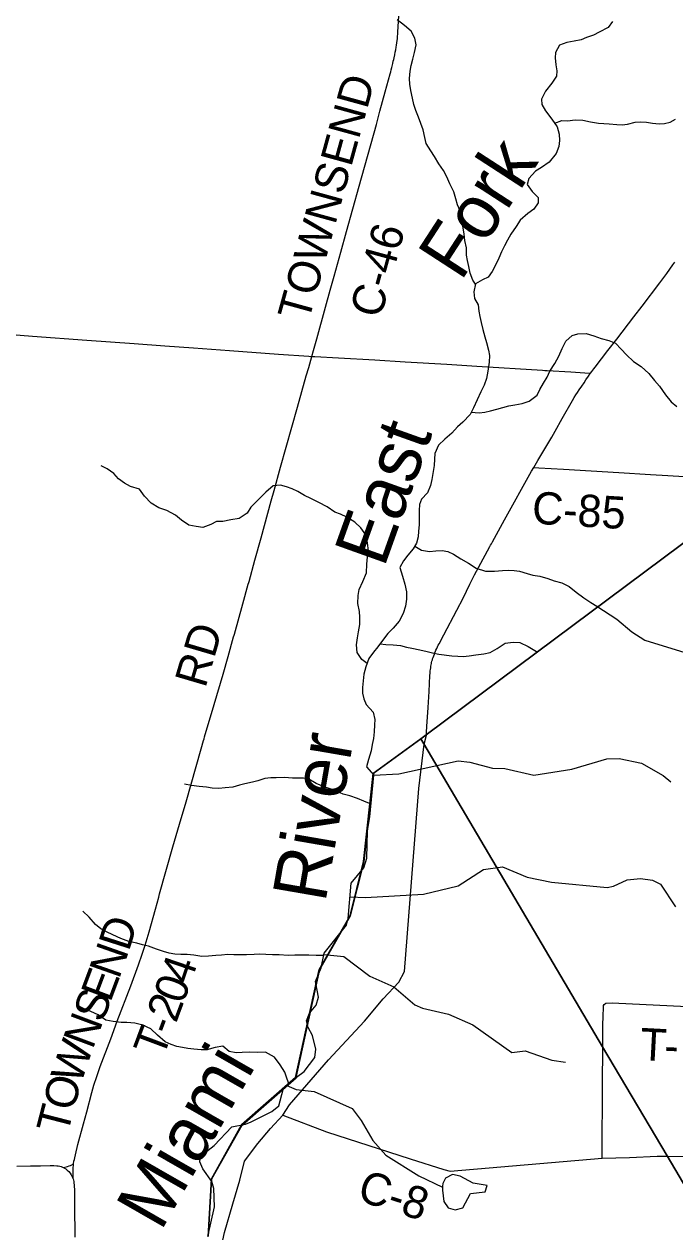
# Model space of a CAD drawing. Extents: x 0 to 1052, y -194 to 246.
# Drawn here: x 2.989 to 4.134, y 15.72 to 17.846 of the extents above; entities that cross this region are included whole.
import ezdxf

# ---------------------------------------------------------------- set-up
doc = ezdxf.new("R2010")
doc.units = 0
for name, color, linetype in [('GM_X_Corporation', 7, 'Continuous'), ('GM_X_County_Road', 7, 'Continuous'), ('GM_X_County_Road_Text', 7, 'Continuous'), ('GM_X_Major_River', 7, 'Continuous'), ('GM_X_Major_River_Text', 7, 'Continuous'), ('GM_X_Minor_Lake', 7, 'Continuous'), ('GM_X_Minor_River', 7, 'Continuous'), ('GM_X_State_Route', 7, 'Continuous'), ('GM_X_Township_Road', 7, 'Continuous'), ('GM_X_Township_Road_Text', 7, 'Continuous')]:
    doc.layers.add(name, color=color, linetype=linetype)

msp = doc.modelspace()

# ---------------------------------------------------------------- linework, layer by layer
at = {"layer": 'GM_X_Corporation'}
for points in [[(5.491, 17.9457), (5.1788, 17.6981), (4.2749, 17.0262), (3.6964, 16.595), (3.6869, 16.5875), (3.6921, 16.5787), (4.0068, 16.0455), (4.1203, 15.8533), (4.4065, 15.3682), (5.0927, 14.2055), (8.7822, 14.2055), (8.7822, 19.8853)], [(4.2749, 17.0262), (3.6964, 16.595), (3.6869, 16.5875), (3.603, 16.5265), (3.586, 16.3718), (3.5622, 16.2766), (3.508, 16.1818), (3.4664, 15.9915), (3.3714, 15.908), (3.3184, 15.8132), (3.3123, 15.7116)], [(3.3123, 15.7116), (3.3184, 15.8132), (3.3714, 15.908), (3.4664, 15.9915), (3.508, 16.1818), (3.5622, 16.2766), (3.586, 16.3718), (3.603, 16.5265), (3.6869, 16.5875), (3.6964, 16.595), (4.2749, 17.0262)], [(3.3123, 15.7116), (3.3184, 15.8132), (3.3714, 15.908), (3.4664, 15.9915), (3.508, 16.1818), (3.5622, 16.2766), (3.586, 16.3718), (3.603, 16.5265), (3.6869, 16.5875), (3.6964, 16.595), (4.2749, 17.0262)], [(4.4065, 15.3682), (4.1203, 15.8533), (4.0068, 16.0455), (3.6921, 16.5787), (3.6869, 16.5875), (3.603, 16.5265), (3.586, 16.3718), (3.5622, 16.2766), (3.508, 16.1818), (3.4664, 15.9915), (3.3714, 15.908), (3.3184, 15.8132), (3.3123, 15.7116)]]:
    msp.add_lwpolyline(points, dxfattribs=at)
at = {"layer": 'GM_X_County_Road'}
for points in [[(3.4947, 17.261), (3.4976, 17.2712), (3.5035, 17.2921), (3.5189, 17.3478), (3.5274, 17.3777), (3.534, 17.4023), (3.5459, 17.4448), (3.5558, 17.4807), (3.5783, 17.5609), (3.6085, 17.6692), (3.6147, 17.6926), (3.6241, 17.7267), (3.6327, 17.7585), (3.6337, 17.7621), (3.6346, 17.7659), (3.6355, 17.7695), (3.6373, 17.7768), (3.6383, 17.7808), (3.639, 17.784), (3.6396, 17.787), (3.6408, 17.7923), (3.6417, 17.7966), (3.6426, 17.8011), (3.6434, 17.8054), (3.644, 17.8089), (3.6446, 17.8131), (3.6451, 17.8171), (3.6455, 17.82), (3.6459, 17.8246), (3.6463, 17.8286), (3.6466, 17.8318), (3.6482, 17.8609)], [(2.9236, 17.303), (3.0035, 17.2967), (3.099, 17.2899), (3.182, 17.2838), (3.2365, 17.2798), (3.2867, 17.2762), (3.3499, 17.2714), (3.4361, 17.2652), (3.4894, 17.2613), (3.4947, 17.261)], [(3.4947, 17.261), (3.5005, 17.2607), (3.5421, 17.2585), (3.606, 17.2549), (3.6593, 17.2516), (3.7325, 17.2473), (3.7852, 17.2438), (3.9011, 17.2367), (3.9049, 17.2365), (3.9092, 17.2363), (3.9508, 17.2339), (3.9756, 17.2322), (3.9855, 17.2313)], [(3.8855, 17.0657), (3.8945, 17.0651), (3.9379, 17.0625), (4.0353, 17.0565), (4.0912, 17.053), (4.1216, 17.0513), (4.2171, 17.0454), (4.245, 17.0437), (4.2555, 17.0431), (4.2636, 17.0425), (4.2655, 17.0423), (4.2672, 17.0418), (4.2696, 17.0409), (4.2711, 17.04), (4.2725, 17.0387), (4.2735, 17.0372), (4.274, 17.0361), (4.2745, 17.0349), (4.2748, 17.0338), (4.2751, 17.0325), (4.2753, 17.0297), (4.2751, 17.0257)], [(3.4438, 15.9251), (3.5208, 15.8958), (3.6683, 15.8481), (3.7274, 15.8293), (3.7384, 15.8266), (4.0062, 15.8493), (4.054, 15.8506), (4.1026, 15.853), (4.1205, 15.8527), (4.2609, 15.8504)], [(2.9759, 15.8354), (2.9995, 15.8359), (3.0175, 15.8362), (3.0343, 15.8365), (3.0411, 15.8364), (3.046, 15.8362), (3.0484, 15.8358), (3.0514, 15.8353), (3.0537, 15.8346), (3.056, 15.8338), (3.0579, 15.8328)], [(3.0579, 15.8328), (3.0587, 15.8324), (3.0617, 15.8306), (3.0646, 15.8283), (3.0672, 15.8258), (3.0695, 15.823), (3.0715, 15.82), (3.0731, 15.8167), (3.0746, 15.8129)], [(3.0746, 15.8129), (3.0758, 15.8081), (3.0762, 15.8057), (3.0766, 15.8026), (3.0769, 15.7989), (3.0771, 15.7946), (3.0774, 15.7661), (3.0779, 15.7101)]]:
    msp.add_lwpolyline(points, dxfattribs=at)
at = {"layer": 'GM_X_Major_River'}
for points in [[(4.0241, 17.8505), (4.0167, 17.8404), (4.0009, 17.832), (3.9906, 17.8265), (3.9783, 17.8226), (3.9688, 17.8186), (3.9569, 17.8158), (3.944, 17.8138), (3.931, 17.8091), (3.9239, 17.7964), (3.9233, 17.7865), (3.9242, 17.7744), (3.9259, 17.7637), (3.9253, 17.7542), (3.9174, 17.7422), (3.9061, 17.728), (3.899, 17.7141), (3.8999, 17.7046), (3.9065, 17.6935), (3.9176, 17.6789), (3.9268, 17.6654), (3.93, 17.6524), (3.9308, 17.641), (3.9299, 17.6308), (3.9247, 17.6184), (3.9126, 17.6031), (3.8991, 17.5938), (3.8887, 17.5872), (3.8771, 17.5742), (3.8738, 17.564), (3.8826, 17.5513), (3.8931, 17.5408), (3.8932, 17.5313), (3.8858, 17.5205), (3.8754, 17.5124), (3.8618, 17.5009), (3.8544, 17.4896), (3.8454, 17.4765), (3.8395, 17.4656), (3.8343, 17.4559), (3.8288, 17.4454), (3.824, 17.4341), (3.8192, 17.4239)], [(3.8192, 17.4239), (3.8125, 17.4104), (3.8051, 17.4007), (3.7951, 17.396), (3.7832, 17.3886), (3.7802, 17.375), (3.7811, 17.3628), (3.7877, 17.3517), (3.789, 17.341), (3.7907, 17.3315), (3.7928, 17.3209), (3.7959, 17.3083), (3.7994, 17.2957), (3.8023, 17.2858), (3.8061, 17.272), (3.8075, 17.2625), (3.8068, 17.2507), (3.805, 17.2352), (3.8024, 17.2224), (3.798, 17.2103), (3.7924, 17.1987), (3.7857, 17.1848), (3.7797, 17.1708), (3.7734, 17.1588), (3.761, 17.1454), (3.7513, 17.1369), (3.7416, 17.1261), (3.7288, 17.1153), (3.7176, 17.1049), (3.7112, 17.0899), (3.711, 17.0804), (3.71, 17.069), (3.7078, 17.0547), (3.7061, 17.0444), (3.7036, 17.0335), (3.6987, 17.0207), (3.6879, 17.0099), (3.6842, 17.0001), (3.6836, 16.9895), (3.6838, 16.9766), (3.6839, 16.9644), (3.6829, 16.9535), (3.6819, 16.9436), (3.6794, 16.9323), (3.6735, 16.9225), (3.6638, 16.9113), (3.656, 16.9012), (3.65, 16.8892), (3.6543, 16.8743), (3.6585, 16.8598), (3.6616, 16.8465), (3.6617, 16.8336), (3.6596, 16.8215), (3.6555, 16.8083), (3.6484, 16.7948), (3.6379, 16.7828), (3.629, 16.7731), (3.6212, 16.7631), (3.611, 16.75), (3.6036, 16.7403), (3.5954, 16.729), (3.5902, 16.7147), (3.5865, 16.7019), (3.5855, 16.6898), (3.5841, 16.678), (3.5839, 16.6682), (3.5863, 16.6579), (3.5903, 16.6483), (3.6029, 16.6348), (3.6056, 16.6218), (3.6054, 16.6123), (3.6048, 16.5998), (3.6034, 16.5881), (3.6013, 16.5775), (3.5992, 16.5669), (3.5947, 16.5514), (3.5914, 16.5382), (3.604, 16.5237)], [(3.3118, 15.7115), (3.3234, 15.7637), (3.3227, 15.796), (3.3187, 15.8086), (3.303, 15.8308), (3.2979, 15.843), (3.2991, 15.8532), (3.3233, 15.8719), (3.3544, 15.9049), (3.378, 15.9095), (3.3883, 15.9132), (3.4246, 15.9317), (3.4368, 15.9415), (3.4444, 15.9706), (3.4567, 15.9837), (3.4812, 16.002), (3.5001, 16.0268), (3.5022, 16.0416), (3.4961, 16.0652), (3.4883, 16.0793), (3.4858, 16.0915), (3.4909, 16.1047), (3.5028, 16.1186), (3.5068, 16.133), (3.5015, 16.1607), (3.5116, 16.1845), (3.5165, 16.2106), (3.5558, 16.2595), (3.5586, 16.2716), (3.564, 16.3334), (3.5867, 16.3608), (3.5919, 16.3774), (3.5932, 16.4256), (3.597, 16.4502), (3.604, 16.5237)], [(3.3131, 15.7113), (3.3192, 15.8129), (3.3722, 15.9077), (3.4672, 15.9911), (3.5089, 16.1815), (3.563, 16.2763), (3.5868, 16.3714), (3.6039, 16.5262)]]:
    msp.add_lwpolyline(points, dxfattribs=at)
at = {"layer": 'GM_X_Minor_Lake'}
for points in [[(3.7248, 15.7934), (3.7272, 15.7729), (3.735, 15.7622), (3.7475, 15.7586), (3.7608, 15.7622), (3.7744, 15.7875), (3.8003, 15.7902), (3.8038, 15.8016), (3.7788, 15.8057), (3.7562, 15.8177), (3.7426, 15.8205), (3.73, 15.8142)], [(3.73, 15.8142), (3.7257, 15.8048), (3.7251, 15.8003), (3.7248, 15.7934)]]:
    msp.add_lwpolyline(points, dxfattribs=at)
at = {"layer": 'GM_X_Minor_River'}
for points in [[(3.7831, 17.3883), (3.7783, 17.3952), (3.7735, 17.4078), (3.7714, 17.4192), (3.7692, 17.4299), (3.7671, 17.4394), (3.7669, 17.4523), (3.7644, 17.4649), (3.763, 17.4763), (3.7613, 17.4873), (3.7591, 17.498), (3.7578, 17.5082), (3.7556, 17.5185), (3.7512, 17.5281), (3.7483, 17.5384), (3.7447, 17.5509), (3.738, 17.5651), (3.7325, 17.5773), (3.7266, 17.5884), (3.7187, 17.5999), (3.7106, 17.6133), (3.7046, 17.6232), (3.6961, 17.6362), (3.6939, 17.6465), (3.6911, 17.6598), (3.687, 17.6709), (3.6826, 17.6823), (3.6782, 17.6942), (3.6746, 17.7048), (3.6721, 17.7155), (3.6692, 17.7292), (3.6674, 17.7402), (3.6668, 17.7505), (3.6678, 17.763), (3.6698, 17.7732), (3.6726, 17.7846), (3.6758, 17.7959), (3.6783, 17.8099), (3.6765, 17.8214), (3.6698, 17.8336), (3.6578, 17.8436), (3.6454, 17.8536)], [(3.9224, 17.6718), (3.9351, 17.6764), (3.945, 17.6759), (3.9587, 17.6776), (3.972, 17.6771), (3.9856, 17.6738), (3.9993, 17.6718), (4.0087, 17.6709), (4.0182, 17.6704), (4.0315, 17.6691), (4.041, 17.669), (4.0505, 17.67), (4.0639, 17.6732), (4.0737, 17.6738), (4.084, 17.6737), (4.0946, 17.6717), (4.106, 17.6708), (4.1159, 17.671), (4.1254, 17.6736), (4.135, 17.6787)], [(3.7756, 17.1631), (3.7892, 17.162), (3.7995, 17.163), (3.8097, 17.1651), (3.8208, 17.168), (3.8311, 17.1713), (3.8414, 17.1738), (3.852, 17.1756), (3.865, 17.1781), (3.8776, 17.1825), (3.8918, 17.1926), (3.8965, 17.2027), (3.9027, 17.2141), (3.9093, 17.2246), (3.9136, 17.2348), (3.9225, 17.2483), (3.9299, 17.2612), (3.9358, 17.2751), (3.9421, 17.2879), (3.9532, 17.2977), (3.9631, 17.301), (3.9776, 17.3012), (3.9912, 17.2972), (4.0044, 17.2928), (4.0177, 17.2892), (4.0297, 17.2842), (4.0395, 17.2738), (4.0485, 17.2638), (4.0612, 17.2522), (4.0744, 17.2433), (4.0879, 17.231), (4.098, 17.2184), (4.107, 17.2087), (4.1174, 17.1934), (4.1275, 17.1811), (4.1373, 17.1727)], [(3.5923, 16.7205), (3.5828, 16.7273), (3.5746, 16.74), (3.5733, 16.7533), (3.5753, 16.7658), (3.577, 16.7764), (3.5794, 16.7889), (3.5792, 16.8022), (3.5786, 16.8117), (3.5761, 16.8261), (3.5767, 16.8402), (3.578, 16.8504), (3.585, 16.8647), (3.5909, 16.8798), (3.5919, 16.895), (3.5932, 16.9083), (3.5945, 16.9185), (3.5928, 16.933), (3.5899, 16.9467), (3.5813, 16.9593), (3.5705, 16.9693), (3.5565, 16.9782), (3.5452, 16.9833), (3.5354, 16.9869), (3.5218, 16.9965), (3.5071, 17.0039), (3.4932, 17.0106), (3.4822, 17.0164), (3.4702, 17.0234), (3.4603, 17.0277), (3.4501, 17.0316), (3.4399, 17.0344), (3.427, 17.0334), (3.4139, 17.0222), (3.4004, 17.0084), (3.3874, 16.9956), (3.3811, 16.9851), (3.367, 16.9758), (3.3525, 16.9733), (3.3384, 16.9704), (3.327, 16.9706), (3.3174, 16.9654), (3.3029, 16.9599), (3.2912, 16.9616), (3.2787, 16.964), (3.2655, 16.9729), (3.255, 16.9818), (3.2399, 16.9896), (3.2259, 16.9947), (3.212, 17.0024), (3.2004, 17.0151), (3.1914, 17.0274), (3.1759, 17.0321), (3.165, 17.038), (3.1548, 17.0453), (3.1466, 17.0549), (3.1349, 17.063), (3.1244, 17.0685)], [(3.6761, 16.9269), (3.6879, 16.92), (3.702, 16.9175), (3.713, 16.9189), (3.7244, 16.9195), (3.7346, 16.9175), (3.7444, 16.9128), (3.7572, 16.9046), (3.7704, 16.8969), (3.784, 16.8884), (3.8006, 16.8832), (3.8162, 16.883), (3.8303, 16.8843), (3.8405, 16.885), (3.8508, 16.8844), (3.8606, 16.8832), (3.8739, 16.8788), (3.8841, 16.8757), (3.8962, 16.874), (3.9106, 16.87), (3.9212, 16.8657), (3.9348, 16.8625), (3.9476, 16.8559), (3.9604, 16.8458), (3.9736, 16.8358), (3.986, 16.8277), (3.9964, 16.8212)], [(3.9964, 16.8212), (4.032, 16.7986), (4.0579, 16.7759), (4.0812, 16.7612), (4.1515, 16.7398), (4.1736, 16.7441), (4.2151, 16.7561), (4.2602, 16.7495), (4.309, 16.7357)], [(3.615, 16.7551), (3.6249, 16.7541), (3.6382, 16.7532), (3.6511, 16.7519), (3.6613, 16.7491), (3.6712, 16.7471), (3.6848, 16.7446), (3.6977, 16.7414), (3.7075, 16.739), (3.7185, 16.7366), (3.7413, 16.734), (3.7519, 16.7331), (3.7614, 16.733), (3.7716, 16.734), (3.7834, 16.7354), (3.7975, 16.7375), (3.8086, 16.74), (3.8212, 16.7466), (3.835, 16.756), (3.8495, 16.7577), (3.8612, 16.7575), (3.8759, 16.7505), (3.8901, 16.7413)], [(3.604, 16.5237), (3.648, 16.5262), (3.7526, 16.5489), (3.7731, 16.5467), (3.8128, 16.536), (3.8344, 16.5357), (3.8855, 16.5237), (3.9524, 16.5343), (4.0141, 16.5525), (4.0357, 16.553), (4.0754, 16.545), (4.1135, 16.5233), (4.127, 16.5121)], [(3.5991, 16.4725), (3.5863, 16.4779), (3.5753, 16.4826), (3.5621, 16.4873), (3.5503, 16.4901), (3.5394, 16.4952), (3.5288, 16.4991), (3.5167, 16.5031), (3.5027, 16.509), (3.4899, 16.5167), (3.4801, 16.5187), (3.4702, 16.5185), (3.4607, 16.5186), (3.447, 16.5195), (3.4322, 16.519), (3.4227, 16.5191), (3.4121, 16.5177), (3.3999, 16.5137), (3.3903, 16.5112), (3.377, 16.5087), (3.3675, 16.5062), (3.3557, 16.5029), (3.3423, 16.5012), (3.3313, 16.5002), (3.3195, 16.5007), (3.3093, 16.5024), (3.2964, 16.5037), (3.2831, 16.5057), (3.271, 16.5082)], [(3.5619, 16.3094), (3.5895, 16.3084), (3.6912, 16.314), (3.7525, 16.3292), (3.7969, 16.3575), (3.8307, 16.3624), (3.8741, 16.3444), (3.9165, 16.3352), (4.0146, 16.326), (4.026, 16.3282), (4.0497, 16.3396), (4.0736, 16.342), (4.0944, 16.3391), (4.1088, 16.3321), (4.1348, 16.2919)], [(3.5157, 16.2061), (3.5025, 16.206), (3.4895, 16.2066), (3.4649, 16.2069), (3.4531, 16.2063), (3.4375, 16.2072), (3.4257, 16.2074), (3.414, 16.2083), (3.4033, 16.2084), (3.3935, 16.2082), (3.3802, 16.2076), (3.3695, 16.2074), (3.3574, 16.2075), (3.3471, 16.208), (3.3361, 16.207), (3.3262, 16.206), (3.3129, 16.2051), (3.3011, 16.2048), (3.2871, 16.2069), (3.2753, 16.2078), (3.2643, 16.208), (3.2541, 16.2085), (3.2438, 16.2101), (3.2336, 16.2133), (3.2215, 16.2176), (3.2072, 16.2228), (3.1969, 16.2248), (3.1867, 16.228), (3.1727, 16.2308), (3.1587, 16.2363), (3.1448, 16.2429), (3.1338, 16.248), (3.1236, 16.2531), (3.1139, 16.2608), (3.103, 16.2735), (3.0918, 16.2846)], [(3.516, 16.208), (3.5513, 16.2045), (3.5968, 16.1698), (3.6391, 16.1511), (3.6762, 16.1195), (3.6898, 16.1133), (3.7356, 16.1029), (3.7786, 16.0845), (3.847, 16.0355), (3.8702, 16.0383), (3.9174, 16.0222), (3.9416, 16.0184)], [(3.4542, 15.981), (3.4517, 15.9888), (3.4473, 16.0006), (3.4395, 16.014), (3.4294, 16.027), (3.4132, 16.0363), (3.3987, 16.0354), (3.3858, 16.0359), (3.3725, 16.0357), (3.3619, 16.0347), (3.3494, 16.0375), (3.3381, 16.0468), (3.3248, 16.0443), (3.3099, 16.04), (3.3004, 16.0401), (3.2875, 16.0414), (3.2765, 16.0427), (3.2671, 16.0443), (3.2572, 16.0463), (3.2474, 16.0495), (3.2368, 16.0542), (3.2233, 16.0658), (3.2113, 16.0773), (3.1977, 16.0839), (3.1837, 16.0871), (3.1696, 16.0881), (3.1594, 16.0886), (3.1454, 16.0899), (3.1325, 16.0924), (3.1186, 16.1017), (3.1061, 16.1075), (3.0929, 16.113), (3.0823, 16.1181)], [(3.4509, 15.9775), (3.4675, 15.9703), (3.499, 15.9669), (3.5658, 15.9369), (3.5818, 15.9158), (3.6022, 15.8806), (3.6254, 15.8546), (3.683, 15.8182), (3.725, 15.7984)]]:
    msp.add_lwpolyline(points, dxfattribs=at)
at = {"layer": 'GM_X_State_Route'}
for points in [[(3.6966, 16.5945), (3.6969, 16.5993), (3.6974, 16.6093), (3.6996, 16.6428), (3.7014, 16.6713), (3.7028, 16.6992), (3.7032, 16.7034), (3.7035, 16.7072), (3.7037, 16.7098), (3.7042, 16.7129), (3.7045, 16.7154), (3.7049, 16.7178), (3.7054, 16.7204), (3.7058, 16.7221), (3.7064, 16.7245), (3.7071, 16.7267), (3.7076, 16.7288), (3.7084, 16.7308), (3.7095, 16.7341), (3.7106, 16.737), (3.7115, 16.7392), (3.7127, 16.7422), (3.7134, 16.744), (3.7149, 16.747), (3.7163, 16.7499), (3.7175, 16.7524), (3.7189, 16.7551), (3.727, 16.7706), (3.7502, 16.8145), (3.7612, 16.8354), (3.7733, 16.8599), (3.7815, 16.8766), (3.7885, 16.8896), (3.8082, 16.9264), (3.8097, 16.929), (3.811, 16.9312), (3.8128, 16.9346), (3.8339, 16.9732), (3.8488, 16.9997), (3.8671, 17.0329), (3.8816, 17.059), (3.8855, 17.0657), (3.8926, 17.0778), (3.9171, 17.1188), (3.9233, 17.1295), (3.9354, 17.1519), (3.9539, 17.1836), (3.9568, 17.1885), (3.9596, 17.1933), (3.9625, 17.1975), (3.9657, 17.2023), (3.97, 17.2087), (3.974, 17.2146), (3.9773, 17.2196), (3.9819, 17.2263), (3.9851, 17.2308), (3.9855, 17.2313), (3.988, 17.2347), (3.9911, 17.2389), (3.9936, 17.2423), (4.0161, 17.2713), (4.0319, 17.2913), (4.0615, 17.3305), (4.0762, 17.3497), (4.1077, 17.3905), (4.1199, 17.407), (4.1306, 17.4222), (4.134, 17.4272)], [(3.3309, 15.6626), (3.3336, 15.6833), (3.3412, 15.7185), (3.3559, 15.7688), (3.3684, 15.8107), (3.3766, 15.8444), (3.3998, 15.8752), (3.4222, 15.9019), (3.4438, 15.9251), (3.4554, 15.9436), (3.5244, 16.0224), (3.5876, 16.0907), (3.6204, 16.1297), (3.6481, 16.1593), (3.6582, 16.1782), (3.6834, 16.5002), (3.6924, 16.5782), (3.6966, 16.5945)]]:
    msp.add_lwpolyline(points, dxfattribs=at)
at = {"layer": 'GM_X_Township_Road'}
for points in [[(3.0756, 15.8396), (3.0763, 15.844), (3.077, 15.8473), (3.0777, 15.8501), (3.0788, 15.8555), (3.0832, 15.8736), (3.093, 15.9102), (3.0987, 15.9312), (3.1076, 15.9648), (3.1113, 15.9779), (3.1163, 15.9933), (3.1226, 16.0108), (3.1412, 16.0596), (3.1526, 16.0905), (3.1762, 16.1526), (3.1899, 16.1899), (3.1965, 16.2087), (3.2016, 16.2247), (3.2084, 16.248), (3.2198, 16.288), (3.2254, 16.3089), (3.2263, 16.312), (3.2271, 16.3148), (3.2504, 16.3975), (3.262, 16.4375), (3.2736, 16.4768), (3.3, 16.5701), (3.3042, 16.5846), (3.3052, 16.588), (3.3061, 16.5912), (3.3229, 16.6482), (3.3386, 16.7019), (3.3475, 16.7329), (3.3573, 16.7674), (3.358, 16.77), (3.3587, 16.7723), (3.3733, 16.8257), (3.3831, 16.8602), (3.3838, 16.8628), (3.3845, 16.865), (3.3946, 16.9023), (3.4056, 16.9418), (3.4233, 17.0065), (3.4284, 17.0251), (3.4397, 17.0658), (3.4696, 17.1716), (3.4852, 17.2266), (3.4895, 17.2415), (3.4947, 17.261)], [(4.0069, 16.0381), (4.007, 16.045), (4.0074, 16.0808), (4.0075, 16.1024), (4.0083, 16.1119), (4.0083, 16.118), (4.0095, 16.1202), (4.0122, 16.1225), (4.0235, 16.1232), (4.2038, 16.1141), (4.211, 16.1159), (4.2137, 16.1254), (4.2393, 16.5447), (4.2588, 16.8595), (4.2751, 17.0257)], [(4.0062, 15.8493), (4.0063, 15.9855), (4.0069, 16.0381)], [(3.0579, 15.8328), (3.0624, 15.8341), (3.0649, 15.8348), (3.0677, 15.8357), (3.07, 15.8365), (3.0716, 15.8374), (3.0756, 15.8396)], [(3.0746, 15.8129), (3.075, 15.8175), (3.0751, 15.8203), (3.0751, 15.8245), (3.075, 15.8282), (3.0749, 15.8306), (3.075, 15.8331), (3.0752, 15.8365), (3.0756, 15.8396)]]:
    msp.add_lwpolyline(points, dxfattribs=at)

# ---------------------------------------------------------------- texts
at = {"layer": 'GM_X_County_Road_Text'}
for s, rotation, p in [('TOWNSEND', 74.606, (3.489, 17.3204)), ('C-46', 74.6575, (3.6158, 17.3262)), ('C-85', 356.5725, (3.8813, 16.9668)), ('C-8', 342.2913, (3.5725, 15.7759))]:
    msp.add_text(s, height=0.05682, rotation=rotation, dxfattribs=at).set_placement(p)
at = {"layer": 'GM_X_Major_River_Text'}
for s, rotation, p in [('Fork', 57.0271, (3.7572, 17.3915)), ('East', 70.3043, (3.6219, 16.8873)), ('River', 80.1789, (3.5186, 16.2978)), ('Miami', 60.1802, (3.2292, 15.7192))]:
    msp.add_text(s, height=0.0947, rotation=rotation, dxfattribs=at).set_placement(p)
at = {"layer": 'GM_X_Township_Road_Text'}
for s, height, rotation, p in [('RD', 0.05682, 73.5814, (3.3074, 16.6756)), ('D', 0.0568, 72.2967, (3.1727, 16.2121)), ('N', 0.0568, 70.5896, (3.1555, 16.1632)), ('E', 0.0568, 69.421, (3.1402, 16.1222)), ('4', 0.0568, 71.1042, (3.2807, 16.1531)), ('0', 0.0568, 69.9351, (3.2683, 16.1191)), ('S', 0.0568, 69.3527, (3.1266, 16.0863)), ('2', 0.0568, 69.6437, (3.256, 16.086)), ('N', 0.0568, 69.4346, (3.1091, 16.0395)), ('T', 0.0568, 69.5237, (3.2329, 16.0242)), ('-', 0.0568, 69.548, (3.2478, 16.064)), ('T', 0.0568, 357.0288, (4.0716, 16.0222)), ('W', 0.0568, 71.2728, (3.0881, 15.9776)), ('-', 0.0568, 357.1974, (4.1142, 16.02)), ('O', 0.0568, 74.8637, (3.0753, 15.9302)), ('T', 0.0568, 75.5282, (3.0647, 15.8892))]:
    msp.add_text(s, height=height, rotation=rotation, dxfattribs=at).set_placement(p)

doc.saveas('drawing.dxf')
